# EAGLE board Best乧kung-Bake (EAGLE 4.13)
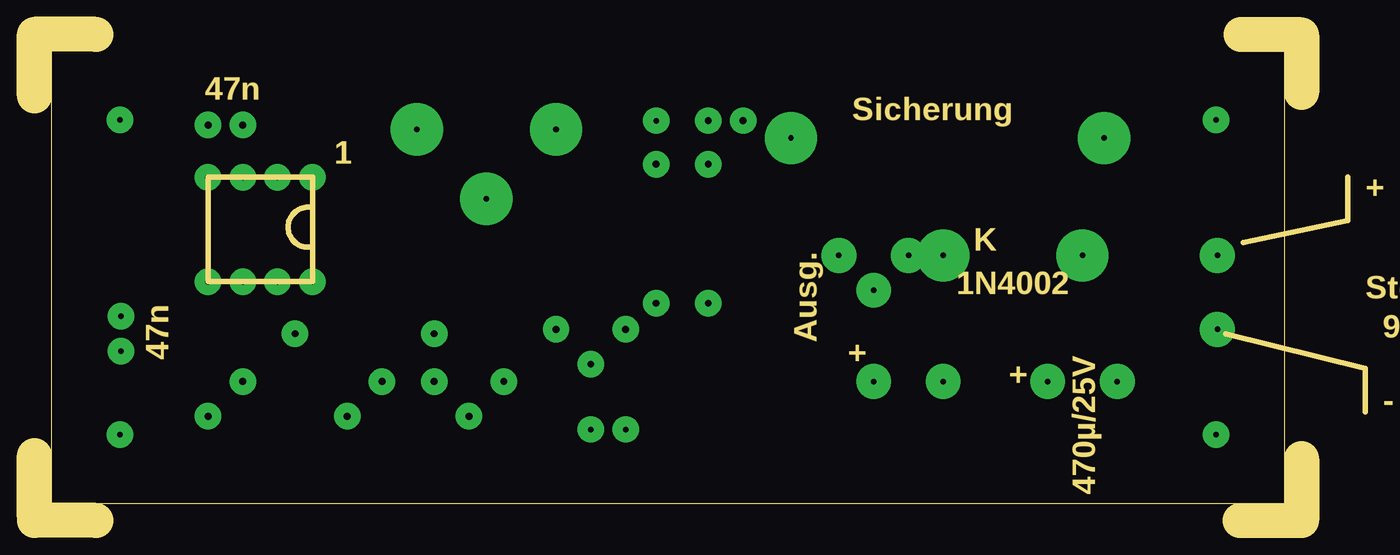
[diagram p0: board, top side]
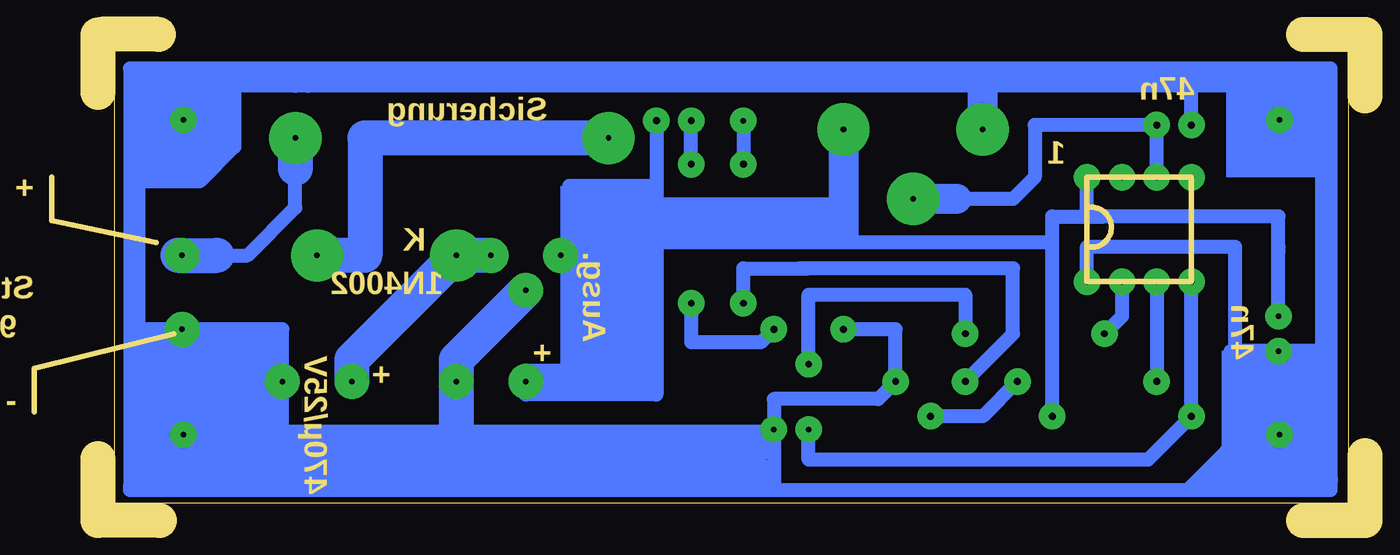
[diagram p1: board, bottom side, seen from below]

Size 97.14 x 35.5 mm. Coordinates in mm from the lower left corner, seen from the top.
Outline: 91.25,34.25 91.25,1.25 1.25,1.25 1.25,34.25
Outline: 0,31 0,35.5 4.5,35.5
Outline: 0,0.25 0,4.75
Outline: 4.5,0 0,0
Outline: 92.5,35.43 92.5,31.25
Outline: 92.5,4.5 92.5,0 88,0
Outline: 88.07,35.5 92.25,35.5
Outline: 20.3,22.84 20.3,25.06 12.68,25.06 12.68,17.44 20.3,17.44 20.3,19.98
Outline: 20.3,22.84 20.3,19.98
Outline: 20.3,19.98 arc-205 20.3,22.84
Outline: 88.25,20.3 95.86,21.89 95.86,25.06
Outline: 86.97,13.63 97.14,11.09 97.14,7.92
Copper layers (1*16): Top 0.035mm / dielectric 1.5mm / Bottom 0.035mm
Design rules "default": minimum track width 10mil, minimum drill 24mil, track to track 8mil, track to pad 8mil, pad to pad 8mil, via to via 8mil, smd to smd 8mil, copper to edge 40mil, drill to drill 8mil, minimum pad ring 10mil, minimum via ring 8mil, stop-mask expansion 4mil, vias tented up to drill 0mil, thermal gap 10mil

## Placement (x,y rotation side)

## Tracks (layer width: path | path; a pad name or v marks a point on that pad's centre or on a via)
S$1  (via drill 0.4 pad 1.93)
  other vias: 6.25,6.25
S$2  (via drill 0.4 pad 1.93)
  other vias: 6.25,29.25
S$3  (via drill 0.4 pad 1.93)
  other vias: 86.25,6.25
S$4  (via drill 0.4 pad 1.93)
  other vias: 86.25,29.25
S$6  (via drill 0.4 pad 2.54)
  Bottom 1.016: 52.05,19.35 v58.72,19.35
S$7  (via drill 0.4 pad 1.93, 0.5 pad 1.93)
  Bottom 1.016: v15.22,17.44 v15.22,10.14
S$8  (via drill 0.4 pad 1.93)
  other vias: 43.16,6.65
S$9  (via drill 0.4 pad 1.93)
  Bottom 1.016: v20.3,17.44 20.3,19.98 9.51,19.98 9.51,12.04
S$10  (via drill 0.4 pad 1.93)
  other vias: 12.68,25.06
S$11
  Bottom 1.016: 89.83,24.75 85.07,24.75 82.53,27.29 82.53,31.73 | 82.53,31.73 82.53,32.36 | 77.13,31.73 78.08,31.73 | 77.13,31.73 82.53,31.73 | 9.19,31.73 77.13,31.73
S$12
  Bottom 1.016: 52.05,24.43 58.08,24.43
S$13  (via drill 0.5 pad 1.93)
  Bottom 1.016: v38.08,13.95 34.27,13.95 v34.27,10.14 35.54,8.87 43.16,8.87 43.16,2.52
S$14  (via drill 0.4 pad 1.93, 0.5 pad 1.93)
  Bottom 1.016: v45.38,29.19 v45.38,26.02
S$15  (via drill 0.5 pad 1.93)
  Bottom 1.016: v49.19,26.02 v49.19,29.19
S$16  (via drill 0.4 pad 1.93)
  other vias: 17.76,25.06
S$17  (via drill 0.4 pad 1.93)
  other vias: 6.33,12.36
S$18  (via drill 0.4 pad 2.54, 0.4 pad 3.81)
  Bottom 1.016: v86.34,19.35 83.8,19.35 81.58,19.35 78.08,22.84 78.08,25.7
  Bottom 2.54: v78.08,27.92 78.08,25.7 | 86.66,19.35 83.8,19.35
S$19  (via drill 0.5 pad 1.93)
  other vias: 15.22,28.87
S$20  (via drill 0.4 pad 3.81)
  Bottom 1.016: 73,19.35 v76.5,19.35
  Bottom 2.54: v55.23,27.92 73,27.92 73,19.35 76.81,19.35
S$21  (via drill 0.5 pad 1.93)
  Bottom 1.016: v51.73,29.19 51.73,22.52 51.73,9.19 61.26,9.19
  Bottom 2.184: 51.73,22.52 38.4,22.52
S$22  (via drill 0.4 pad 2.54)
  Bottom 1.016: 89.52,24.11 89.52,13.95 v86.34,13.95 79.04,13.95 v79.04,10.14 79.04,3.79 63.8,3.79
S$23  (via drill 0.4 pad 1.93, 0.5 pad 1.93)
  Bottom 1.016: v20.3,25.06 20.3,22.2 19.03,22.2 | 19.03,22.2 6.33,22.2 6.33,19.66 | 6.33,19.66 6.33,19.98 | v6.33,14.9 6.33,19.66 | v22.84,7.6 22.84,20.3 | 22.84,20.3 22.84,22.2 19.03,22.2 | 22.84,20.3 52.37,20.3
S$24  (via drill 0.4 pad 1.93, 0.41 pad 3.81)
  Bottom 1.016: v15.22,25.06 15.22,28.87 24.11,28.87 24.11,25.06 25.7,23.48 27.6,23.48 | 27.29,23.48 27.6,23.48 | 27.6,23.48 29.82,23.48
  Bottom 2.184: 29.82,23.48 v33,23.48
S$25  (via drill 0.5 pad 1.93)
  Bottom 1.016: v12.68,28.87 12.68,32.36
S$26  (via drill 0.5 pad 1.93)
  Bottom 1.016: v43.16,13.95 44.11,13 49.19,13 v49.19,15.86
S$27
  Bottom 2.54: 61.58,4.42 44.11,5.7 78.72,5.7
S$28  (via drill 0.4 pad 1.93, 0.5 pad 1.93)
  Bottom 1.016: v12.68,17.44 v12.68,7.6 15.86,4.42 20.62,4.42 | v40.62,6.65 40.62,4.42 36.81,4.42 | 36.81,4.42 37.45,4.42 | 19.66,4.42 20.62,4.42 | 20.62,4.42 36.81,4.42
S$29  (via drill 0.5 pad 1.93)
  Bottom 1.016: v25.38,10.14 27.92,7.6 v31.73,7.6
S$31  (via drill 0.4 pad 2.54, 0.4 pad 3.81)
  Bottom 1.016: v63.8,19.35 v66.34,19.35
  Bottom 2.54: v63.8,19.35 v66.34,19.35 73.96,11.73 v73.96,10.14
S$32  (via drill 0.4 pad 2.54)
  Bottom 2.54: v61.26,16.81 66.34,11.73 66.34,6.33
S$33  (via drill 0.4 pad 2.54)
  other vias: 66.34,10.14
S$34
  Bottom 1.016: 9.82,12.36 3.16,12.36 3.16,33 3.47,33 | 90.15,2.52 90.15,33 3.47,33 | 3.47,33 2.52,33 2.52,3.16 | 2.52,3.16 2.52,2.84 | 2.52,3.16 2.52,2.2 14.27,2.2 | 14.27,2.2 90.15,2.2 | 10.14,5.06 13,2.2 14.27,2.2
S$35  (via drill 0.4 pad 1.93, 0.5 pad 1.93)
  Bottom 1.016: v17.76,17.44 17.76,14.9 v19.03,13.63
S$36  (via drill 0.5 pad 1.93)
  Bottom 1.016: v29.19,10.14 25.7,13.63 25.7,18.39 40.62,18.39 | 40.62,18.39 41.26,18.39 | v45.38,15.86 45.38,18.39 40.62,18.39
S$38  (via drill 0.5 pad 1.93)
  Bottom 1.016: v40.62,11.41 40.62,16.49 29.19,16.49 v29.19,13.63
S$39  (via drill 0.4 pad 2.54)
  Bottom 2.54: 53,10.14 v61.26,10.14
S$42  (via drill 0.41 pad 3.81)
  Bottom 1.016: 27.92,32.05 27.92,32.36
  Bottom 2.184: v27.92,28.55 27.92,32.05
S$91  (via drill 0.41 pad 3.81)
  Bottom 1.016: 38.08,20.93 52.05,21.57
  Bottom 2.184: v38.08,28.55 38.08,20.93 52.37,21.89
(copper drawn outside any net)
  shapes: Bottom area x15

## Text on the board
Vias: Auf Bestückungsseite gesehen !
Dimension: K | 47n | Sicherung | 1 | + | K | 1N4002 | Steckernetzteil | Ausg. | 9V oder 12V | 47n | + | + | - | 470µ/25V | Cevausit 1,5mm dick | alles mit 0,8mm vorgebohrt | Aufbohren wie folgt:
tOrigins: 78L05 | 1N4002 | Katode | Anode | Ausg. | Eing. | Morse-Tempo | Masse | CW-Ausgang | LED | +5Volt | BC547c | 5K | µA78L05 | 470 | Drossel | E | PIC12F675 | 27K | 18K | E | BC547c | C | E | 10K | B | BC547c | 100µ/63V | LED | Schalter | oder | Diode 1N4002 1,0mm | hier an RA1 von | µA78L05 1,0mm | der DCF77-Schaltuhr | Anschluß-Drähte 1,0mm | Sicherungshalter 1,5mm | Einstellregler 1,2mm | langer | 4Stck. Befestigungsbohr... 3,2mm | Anschluß- | draht | an +5V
